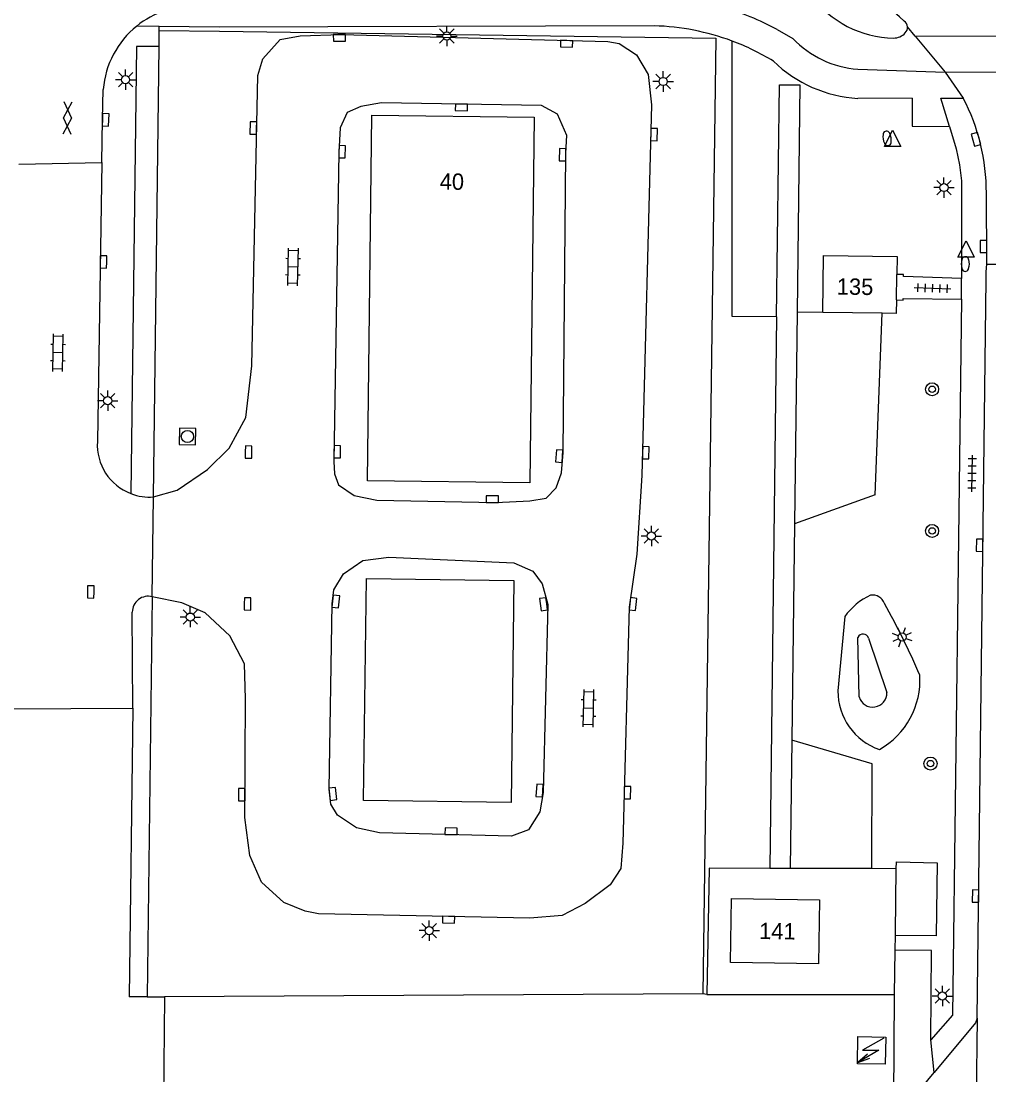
# Model space of a CAD drawing. Extents: x 131000 to 133013, y 393000 to 396501.
# Drawn here: x 132228.2 to 132287.4, y 394920.3 to 394984.9 of the extents above; entities that cross this region are included whole.
import ezdxf

# ---------------------------------------------------------------- set-up
doc = ezdxf.new("R2010")
doc.units = 0
for name, color, linetype in [('gg-afsc-hekwerk', 7, 'Continuous'), ('gg-anno-huisnummerreeks BGT', 7, 'Continuous'), ('gg-bbg-bijgebouw', 7, 'Continuous'), ('gg-bbg-hoofdgebouw', 7, 'Continuous'), ('gg-bbg-lage trafo', 7, 'Continuous'), ('gg-knt-bovenkant onderkant talud', 7, 'Continuous'), ('gg-knt-verharding', 7, 'Continuous'), ('gg-knt-verharding nz', 7, 'Continuous'), ('gt-grn-groengrens', 7, 'Continuous'), ('gt-grn-vlakafsluiter', 7, 'Continuous'), ('gt-grn-weggrens', 7, 'Continuous'), ('gt-symb-boom', 7, 'Continuous'), ('gt-symb-brandkraan', 7, 'Continuous'), ('gt-symb-gesloten verharding', 7, 'Continuous'), ('gt-symb-klinker verharding', 7, 'Continuous'), ('gt-symb-kolk', 7, 'Continuous'), ('gt-symb-lichtmast', 7, 'Continuous'), ('gt-symb-rioolschacht', 7, 'Continuous'), ('gt-symb-tegel verharding', 7, 'Continuous'), ('gt-symb-trafo symbool', 7, 'Continuous'), ('gt-symb-waterafsluiter', 7, 'Continuous')]:
    doc.layers.add(name, color=color, linetype=linetype)

# ---------------------------------------------------------------- blocks, each defined once
blk = doc.blocks.new('gt0-KOLK')
at = {"layer": 'gt-symb-kolk'}
blk.add_lwpolyline([(0, 0), (0.375, 0), (0.375, 0.4), (-0.375, 0.4), (-0.375, 0), (0, 0)], dxfattribs=at)
blk = doc.blocks.new('gt0-LMAST')
at = {"layer": 'gt-symb-lichtmast'}
for p, q in [((-0.182, 0.173), (-0.447, 0.438)), ((-0.005, 0.246), (-0.005, 0.621)), ((0.172, 0.173), (0.437, 0.438)), ((-0.255, -0.004), (-0.63, -0.004)), ((-0.182, -0.181), (-0.447, -0.446)), ((-0.005, -0.254), (-0.005, -0.629)), ((0.437, -0.446), (0.172, -0.181)), ((0.245, -0.004), (0.62, -0.004))]:
    blk.add_line(p, q, dxfattribs=at)
blk.add_circle((-0.005, -0.004), 0.25, dxfattribs=at)
blk = doc.blocks.new('gt0-GESVH1')
at = {"layer": 'gt-symb-gesloten verharding'}
for p, q in [((-0.992, -0.261), (0.008, 0.239)), ((0.008, -0.261), (-0.992, 0.239)), ((0.008, 0.239), (1.008, -0.261)), ((1.008, 0.239), (0.008, -0.261))]:
    blk.add_line(p, q, dxfattribs=at)
blk = doc.blocks.new('gt0-WAFSL')
at = {"layer": 'gt-symb-waterafsluiter'}
for p, q in [((-0.5, -0.333), (0, 0.667)), ((0, 0.667), (0.5, -0.333)), ((0.5, -0.333), (-0.5, -0.333))]:
    blk.add_line(p, q, dxfattribs=at)
blk = doc.blocks.new('gt0-BR')
at = {"layer": 'gt-symb-brandkraan'}
for centre, radius, start, end in [((-0.244, 0), 0.206, 107.56694, 252.43307), ((0.599, -2.664), 3, 106.89205, 107.56694), ((0, -0.691), 0.938, 73.10799, 106.89205), ((-0.599, -2.664), 3, 72.43309, 73.10799), ((0.244, 0), 0.206, 287.56695, 72.43309), ((0.599, 2.664), 3, 252.43307, 253.10797), ((0, 0.691), 0.938, 253.10797, 286.89206), ((-0.599, 2.664), 3, 286.89206, 287.56695)]:
    blk.add_arc(centre, radius, start, end, dxfattribs=at)
blk = doc.blocks.new('gt0-BOOM')
at = {"layer": 'gt-symb-boom'}
for radius in [0.4, 0.2]:
    blk.add_circle((0, 0), radius, dxfattribs=at)
blk = doc.blocks.new('gt0-TEG1')
at = {"layer": 'gt-symb-tegel verharding'}
for p, q in [((-1.125, 0), (1.125, 0)), ((-0.9, -0.25), (-0.9, 0.25)), ((-0.45, -0.25), (-0.45, 0.25)), ((0, -0.25), (0, 0.25)), ((0.45, -0.25), (0.45, 0.25)), ((0.9, -0.25), (0.9, 0.25))]:
    blk.add_line(p, q, dxfattribs=at)
blk = doc.blocks.new('gt0-KL1')
at = {"layer": 'gt-symb-klinker verharding'}
for p, q in [((-1.15, 0.3), (1.15, 0.3)), ((-1, -0.3), (-1, 0.3)), ((-0.5, 0.3), (-0.5, 0.45)), ((0, -0.3), (0, 0.3)), ((0.5, 0.3), (0.5, 0.45)), ((1, -0.3), (1, 0.3)), ((-1.15, -0.3), (1.15, -0.3)), ((-0.5, -0.45), (-0.5, -0.3)), ((0.5, -0.45), (0.5, -0.3))]:
    blk.add_line(p, q, dxfattribs=at)
blk = doc.blocks.new('gt0-RS')
at = {"layer": 'gt-symb-rioolschacht'}
blk.add_lwpolyline([(-0.5, -0.5), (0.5, -0.5), (0.5, 0.5), (-0.5, 0.5)], close=True, dxfattribs=at)
blk.add_circle((0, 0), 0.375, dxfattribs=at)
blk = doc.blocks.new('gt0-HSP')
at = {"layer": 'gt-symb-trafo symbool'}
for points in [[(0.771, 0.746), (-0.529, -0.004), (0.471, -0.004), (-0.829, -0.754)], [(-0.217, -0.24), (-0.829, -0.754), (-0.077, -0.48)]]:
    blk.add_lwpolyline(points, dxfattribs=at)

msp = doc.modelspace()

# ---------------------------------------------------------------- linework, layer by layer
at = {"layer": 'gg-afsc-hekwerk'}
for p, q in [((132236.644, 394983.298), (132236.656, 394984.281)), ((132236.656, 394984.281), (132240.343, 394984.232)), ((132236.303, 394955.707), (132236.644, 394983.298)), ((132236.228, 394949.598), (132236.303, 394955.707)), ((132236.228, 394949.598), (132235.925, 394925.085)), ((132275.282, 394932.956), (132274.028, 394932.958)), ((132280.284, 394932.945), (132275.282, 394932.956)), ((132281.775, 394932.941), (132280.284, 394932.945)), ((132281.723, 394929.024), (132281.775, 394932.941)), ((132281.709, 394927.951), (132281.721, 394928.856)), ((132281.721, 394928.856), (132281.723, 394929.024)), ((132281.673, 394925.226), (132281.709, 394927.951)), ((132269.926, 394925.269), (132236.974, 394925.091)), ((132235.925, 394925.085), (132236.974, 394925.091)), ((132236.974, 394925.091), (132236.466, 394878.195)), ((132270.173, 394925.232), (132281.673, 394925.226)), ((132281.583, 394912.514), (132281.673, 394925.226))]:
    msp.add_line(p, q, dxfattribs=at)
for points in [[(132240.343, 394984.232), (132270.723, 394983.794), (132269.926, 394925.269)], [(132274.028, 394932.958), (132270.313, 394932.967), (132270.173, 394925.232)]]:
    msp.add_lwpolyline(points, dxfattribs=at)
at = {"layer": 'gg-bbg-bijgebouw'}
msp.add_lwpolyline([(132258.2, 394937), (132249.17, 394937.11), (132249.34, 394950.72), (132258.37, 394950.6), (132258.2, 394937)], dxfattribs=at)
at = {"layer": 'gg-bbg-hoofdgebouw'}
for p, q in [((132281.792, 394967.77), (132281.814, 394969.33)), ((132280.915, 394966.952), (132277.28, 394967))]:
    msp.add_line(p, q, dxfattribs=at)
for points in [[(132259.34, 394956.57), (132249.41, 394956.69), (132249.67, 394979.08), (132259.6, 394978.96), (132259.34, 394956.57)], [(132277.28, 394967), (132277.33, 394970.5), (132281.83, 394970.44), (132281.814, 394969.33)], [(132281.792, 394967.77), (132281.78, 394966.94), (132280.915, 394966.952)], [(132277.078, 394931.039), (132277.02, 394927.121), (132271.623, 394927.201), (132271.681, 394931.12), (132277.078, 394931.039)]]:
    msp.add_lwpolyline(points, dxfattribs=at)
at = {"layer": 'gg-bbg-lage trafo'}
msp.add_lwpolyline([(132279.406, 394920.998), (132279.43, 394922.658), (132281.13, 394922.633), (132281.106, 394920.973), (132279.406, 394920.998)], dxfattribs=at)
at = {"layer": 'gg-knt-bovenkant onderkant talud'}
for p, q in [((132278.622, 394948.383), (132278.205, 394943.834)), ((132279.499, 394943.462), (132279.424, 394947.106)), ((132280.08, 394947.062), (132281.2, 394943.73))]:
    msp.add_line(p, q, dxfattribs=at)
for centre, radius, start, end in [((132281.936, 394945.987), 4.09, 115.18611, 144.13799), ((132280.328, 394948.933), 0.766, 19.09275, 99.92936), ((132242.498, 394927.509), 44.229, 22.99077, 29.34487), ((132279.744, 394946.96), 0.351, 16.82406, 155.50142), ((132278.362, 394944.479), 4.862, 299.37922, 3.59275), ((132281.956, 394943.794), 3.751, 179.38765, 251.20024), ((132280.333, 394943.702), 0.868, 196.0735, 1.8337)]:
    msp.add_arc(centre, radius, start, end, dxfattribs=at)
at = {"layer": 'gg-knt-verharding'}
for p, q in [((132236.656, 394984.527), (132235.276, 394984.543)), ((132240.331, 394984.484), (132236.656, 394984.527)), ((132266.964, 394984.559), (132240.331, 394984.484)), ((132274.49, 394984.327), (132275.437, 394983.786)), ((132279.427, 394981.906), (132284.765, 394981.731)), ((132284.765, 394981.731), (132285.878, 394980.13)), ((132282.741, 394980.123), (132279.422, 394980.115)), ((132228.068, 394976.087), (132233.137, 394976.196)), ((132233.137, 394976.196), (132232.87, 394959.099)), ((132287.319, 394969.962), (132287.294, 394974.309)), ((132287.319, 394969.962), (132293.818, 394969.975)), ((132286.732, 394923.791), (132287.283, 394969.039)), ((132235.031, 394942.78), (132235, 394948.658)), ((132227.437, 394942.736), (132235.031, 394942.78)), ((132286.732, 394923.791), (132286.531, 394907.287)), ((132284.094, 394920.452), (132283.89, 394922.451))]:
    msp.add_line(p, q, dxfattribs=at)
for points in [[(132236.303, 394955.707), (132237.762, 394956.116), (132239.617, 394957.393), (132240.937, 394958.695), (132241.956, 394960.568), (132242.318, 394963.742), (132242.686, 394981.512), (132243.002, 394982.545), (132244.062, 394983.726), (132245.278, 394983.953), (132247.786, 394984.036), (132264.117, 394983.592), (132264.818, 394983.469), (132265.872, 394982.779), (132266.579, 394981.587), (132266.787, 394979.728), (132266.209, 394957.027), (132265.886, 394952.196), (132265.421, 394948.963), (132265.033, 394934.507), (132264.904, 394932.95), (132264.264, 394931.952), (132262.724, 394930.799), (132261.319, 394930.081), (132259.349, 394929.919), (132246.397, 394930.174), (132245.586, 394930.344), (132244.276, 394930.86), (132242.923, 394932.123), (132242.193, 394933.741), (132241.905, 394936.077), (132241.937, 394943.35), (132241.873, 394945.485), (132240.977, 394947.201), (132239.457, 394948.614), (132238.033, 394949.232), (132236.228, 394949.598)], [(132233.137, 394976.196), (132233.174, 394978.813), (132233.226, 394980.663)], [(132247.343, 394957.868), (132247.384, 394957.122), (132247.635, 394956.441), (132248.58, 394955.797), (132249.985, 394955.5), (132257.263, 394955.363), (132259.342, 394955.476), (132260.349, 394955.638), (132260.957, 394956.26), (132261.281, 394957.186), (132261.374, 394958.421), (132261.549, 394976.768), (132261.598, 394977.84), (132261.045, 394979.147), (132260.053, 394979.681), (132250.261, 394979.841), (132248.991, 394979.611), (132248.155, 394979.245), (132247.724, 394978.312), (132247.646, 394976.811), (132247.343, 394957.868)], [(132282.741, 394980.123), (132282.758, 394978.417), (132285.032, 394978.395)], [(132285.032, 394978.395), (132285.444, 394977.034), (132285.652, 394976.05), (132285.776, 394975.064), (132285.776, 394969.087)], [(132287.283, 394969.039), (132287.282, 394969.501), (132287.319, 394969.962)], [(132285.776, 394969.087), (132282.21, 394969.2), (132282.21, 394969.32), (132281.814, 394969.33)], [(132281.792, 394967.77), (132282.2, 394967.76), (132282.2, 394967.87), (132285.761, 394967.813)], [(132285.761, 394967.813), (132285.224, 394923.97), (132283.89, 394922.451)], [(132247.235, 394949.152), (132247.345, 394950.009), (132247.932, 394951.004), (132249.117, 394951.817), (132250.71, 394952.011), (132258.373, 394951.681), (132259.526, 394951.156), (132260.101, 394950.385), (132260.438, 394949.121), (132260.157, 394937.611), (132259.955, 394936.423), (132259.266, 394935.317), (132258.218, 394934.939), (132250.134, 394935.139), (132248.728, 394935.436), (132247.563, 394936.228), (132247.152, 394936.9), (132247.048, 394937.804), (132247.235, 394949.152)], [(132286.732, 394923.791), (132286.627, 394923.491), (132284.094, 394920.452)], [(132282.03, 394912.509), (132282.099, 394918.622), (132282.493, 394918.702), (132282.824, 394918.929), (132284.094, 394920.452)]]:
    msp.add_lwpolyline(points, dxfattribs=at)
for centre, radius, start, end in [((132273.476, 394975.487), 12.841, 46.81431, 74.73516), ((132281.699, 394990.124), 6.317, 215.72473, 269.22558), ((132238.811, 394980.155), 5.635, 108.55734, 128.85698), ((132266.608, 394969.786), 16.54, 61.54129, 74.17784), ((132281.985, 394984.462), 0.478, 5.01822, 54.29305), ((132238.776, 394980.212), 5.569, 128.94621, 175.35428), ((132266.526, 394969.699), 14.867, 69.54437, 88.31321), ((132281.61, 394984.769), 0.961, 270.23825, 318.23729), ((132281.985, 394984.463), 0.478, 315.69527, 4.97772), ((132266.5, 394969.655), 14.917, 58.67148, 69.50818), ((132279.889, 394988.06), 6.172, 223.83408, 265.70836), ((132279.901, 394988.188), 8.087, 225.73146, 266.60314), ((132274.769, 394974.345), 12.525, 359.83576, 27.50836), ((132236.071, 394958.905), 3.207, 176.53538, 249.00045), ((132236.071, 394958.912), 3.214, 249.05233, 274.14185), ((132235.988, 394948.64), 0.988, 75.92633, 178.93978)]:
    msp.add_arc(centre, radius, start, end, dxfattribs=at)
at = {"layer": 'gg-knt-verharding nz'}
for p, q in [((132282.942, 394983.926), (132282.461, 394984.504)), ((132282.942, 394983.926), (132299.668, 394983.999)), ((132282.942, 394983.926), (132284.765, 394981.731)), ((132284.765, 394981.731), (132297.558, 394981.787))]:
    msp.add_line(p, q, dxfattribs=at)
at = {"layer": 'gt-grn-groengrens'}
for p, q in [((132236.656, 394984.281), (132236.656, 394984.527)), ((132274.445, 394966.734), (132274.621, 394980.952)), ((132274.445, 394966.734), (132274.028, 394932.958)), ((132275.703, 394967.019), (132275.543, 394954.068)), ((132277.28, 394967), (132275.703, 394967.019)), ((132280.481, 394955.839), (132280.915, 394966.952)), ((132280.481, 394955.839), (132275.543, 394954.068)), ((132275.543, 394954.068), (132275.379, 394940.808)), ((132235.031, 394942.78), (132234.812, 394925.099)), ((132275.379, 394940.808), (132275.282, 394932.956)), ((132280.296, 394939.359), (132275.379, 394940.808)), ((132280.284, 394932.945), (132280.296, 394939.359)), ((132235.925, 394925.085), (132234.812, 394925.099))]:
    msp.add_line(p, q, dxfattribs=at)
for points in [[(132274.445, 394966.734), (132271.736, 394966.767), (132271.722, 394983.628)], [(132236.644, 394983.298), (132235.261, 394983.298), (132234.922, 394955.911)], [(132274.621, 394980.952), (132275.875, 394980.936), (132275.703, 394967.019)], [(132281.775, 394932.941), (132281.787, 394933.369), (132284.278, 394933.297), (132284.215, 394928.823), (132281.721, 394928.856)], [(132283.89, 394922.451), (132283.925, 394927.922), (132281.709, 394927.951)]]:
    msp.add_lwpolyline(points, dxfattribs=at)
at = {"layer": 'gt-grn-vlakafsluiter'}
msp.add_line((132270.173, 394925.232), (132269.926, 394925.269), dxfattribs=at)
at = {"layer": 'gt-grn-weggrens'}
msp.add_line((132285.761, 394967.813), (132285.776, 394969.087), dxfattribs=at)
msp.add_lwpolyline([(132285.032, 394978.395), (132284.508, 394980.127), (132285.878, 394980.13)], dxfattribs=at)

# ---------------------------------------------------------------- block references
at = {"layer": 'gt-symb-boom'}
for p in [(132283.968, 394962.3), (132283.969, 394953.623), (132283.873, 394939.376)]:
    msp.add_blockref('gt0-BOOM', p, dxfattribs=at)
at = {"layer": 'gt-symb-brandkraan'}
for p, rotation in [((132281.218, 394977.669), 98.34123015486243), ((132286.003, 394969.971), 89.31248364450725)]:
    msp.add_blockref('gt0-BR', p, dxfattribs=dict(at, rotation=rotation))
at = {"layer": 'gt-symb-gesloten verharding', "rotation": 88.39613722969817}
msp.add_blockref('gt0-GESVH1', (132231.029, 394978.909), dxfattribs=at)
at = {"layer": 'gt-symb-klinker verharding'}
for p, rotation in [((132244.85, 394969.791), 88.79696545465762), ((132230.455, 394964.539), 89.08334574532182), ((132262.935, 394942.767), 88.79696545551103)]:
    msp.add_blockref('gt0-KL1', p, dxfattribs=dict(at, rotation=rotation))
at = {"layer": 'gt-symb-kolk'}
for p, rotation in [((132247.685, 394984.026), -179.42706130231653), ((132261.6, 394983.66), 178.22439947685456), ((132255.157, 394979.761), 179.08334574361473), ((132233.174, 394978.813), -92.52190794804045), ((132242.618, 394978.301), 88.85423716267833), ((132266.742, 394977.902), -91.77560052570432), ((132286.847, 394977.661), 105.37072543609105), ((132247.652, 394976.856), -91.83467292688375), ((132261.548, 394976.659), 88.85423716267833), ((132287.313, 394971.047), 90.3437705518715), ((132233.442, 394970.1), 89.1406277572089), ((132241.922, 394958.458), -91.14576283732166), ((132247.351, 394958.476), -90.68751635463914), ((132261.347, 394958.197), 86.33074590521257), ((132266.246, 394958.422), -91.66111204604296), ((132257.045, 394955.372), -0.11459140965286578), ((132287.082, 394952.747), 89.31248364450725), ((132232.663, 394949.888), 89.08334574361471), ((132241.862, 394949.16), -91.14576283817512), ((132247.267, 394949.324), -95.45391888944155), ((132260.378, 394949.165), 97.58706906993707), ((132265.462, 394949.171), -96.71987988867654), ((132241.908, 394937.48), 89.94270423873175), ((132247.083, 394937.499), -83.85600423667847), ((132260.137, 394937.716), 85.81229548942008), ((132265.116, 394937.603), -91.20303454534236), ((132254.513, 394935.033), -1.7756005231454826), ((132286.832, 394931.259), 89.31248364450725), ((132254.37, 394930.018), 178.9115111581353)]:
    msp.add_blockref('gt0-KOLK', p, dxfattribs=dict(at, rotation=rotation))
at = {"layer": 'gt-symb-lichtmast'}
for p in [(132254.265, 394983.938), (132234.598, 394981.264), (132267.513, 394981.154), (132284.703, 394974.658), (132233.507, 394961.604), (132266.787, 394953.315), (132238.56, 394948.353), (132253.188, 394929.154), (132284.604, 394925.147)]:
    msp.add_blockref('gt0-LMAST', p, dxfattribs=at)
at = {"layer": 'gt-symb-lichtmast', "rotation": -64.53214455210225}
msp.add_blockref('gt0-LMAST', (132282.14, 394947.124), dxfattribs=at)
at = {"layer": 'gt-symb-rioolschacht', "rotation": -1.4320961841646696}
msp.add_blockref('gt0-RS', (132238.382, 394959.411), dxfattribs=at)
at = {"layer": 'gt-symb-tegel verharding'}
for p, rotation in [((132284.001, 394968.492), -1.8346729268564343), ((132286.416, 394957.143), 88.85423716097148)]:
    msp.add_blockref('gt0-TEG1', p, dxfattribs=dict(at, rotation=rotation))
at = {"layer": 'gt-symb-trafo symbool'}
msp.add_blockref('gt0-HSP', (132280.242, 394921.825), dxfattribs=at)
at = {"layer": 'gt-symb-waterafsluiter'}
for p in [(132281.553, 394977.511), (132286.046, 394970.73)]:
    msp.add_blockref('gt0-WAFSL', p, dxfattribs=at)

# ---------------------------------------------------------------- texts
at = {"layer": 'gg-anno-huisnummerreeks BGT'}
for s, rotation, p in [('40', 359.3, (132253.822, 394974.529)), ('135', 359.2, (132278.131, 394968.101)), ('141', 359.2, (132273.377, 394928.633))]:
    msp.add_text(s, height=1, rotation=rotation, dxfattribs=at).set_placement(p)

doc.saveas('drawing.dxf')
